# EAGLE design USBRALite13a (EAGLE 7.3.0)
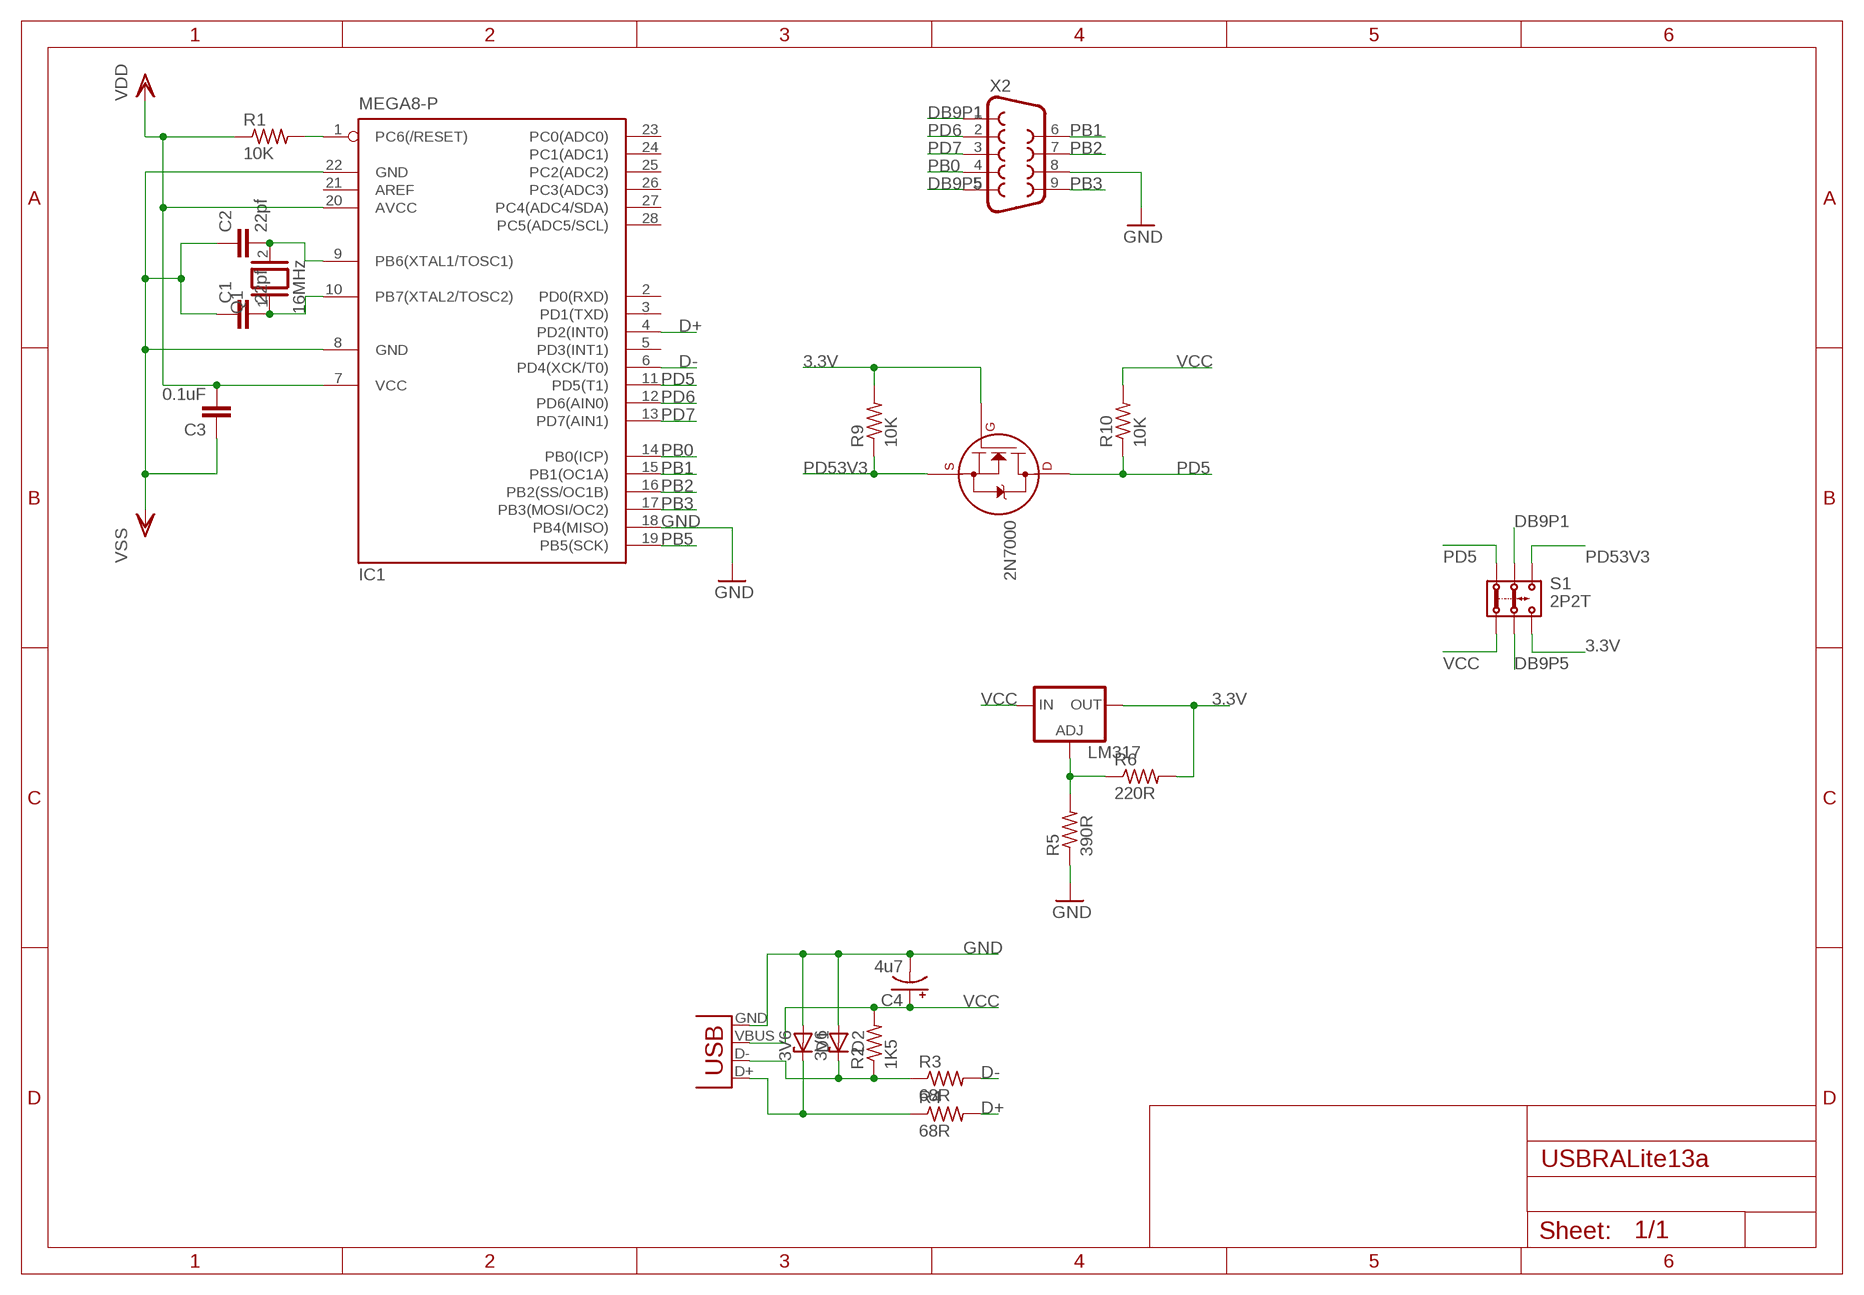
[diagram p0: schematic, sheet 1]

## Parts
2N7000  2N7000_TO92  [TO-92]
C1  22pf  C-EU050-024X044  [C050-024X044]
C2  22pf  C-EU050-024X044  [C050-024X044]
C3  0.1uF  C-EU050-024X044  [C050-024X044]
C4  4u7  CPOL-USE2.5-6  [E2,5-6]
D1  3V6  ZENER-DIODEZD-5  [ZDIO-5]
D2  3V6  ZENER-DIODEZD-5  [ZDIO-5]
IC1  MEGA8-P  [DIL28-3]
LM317  LM317TS  [317TS]
Q1  16MHz  XTAL/S  [QS]
R1  10K  R-US_0207/10  [0207/10]
R2  1K5  R-US_0207/10  [0207/10]
R3  68R  R-US_0207/10  [0207/10]
R4  68R  R-US_0207/10  [0207/10]
R5  390R  R-US_0207/10  [0207/10]
R6  220R  R-US_0207/10  [0207/10]
R9  10K  R-US_0207/10  [0207/10]
R10  10K  R-US_0207/10  [0207/10]
S1  2P2T  [2P2T]
X1  USBPTH  [USB-B-PTH]
X2  DB9MALE  [DB9_MALE]

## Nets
3.3V: 2N7000.2(G) LM317.2(OUT) R6.2 R9.2 S1.3.2
D+: IC1.4(PD2(INT0)) R4.2
D-: IC1.6(PD4(XCK/T0)) R3.2
DB9P1: S1.2.1 X2.1
DB9P5: S1.2.2 X2.5
GND: C1.1 C2.1 C3.1 C4.- D1.A D2.A IC1.8(GND) IC1.18(PB4(MISO)) IC1.22(GND) R5.1 X1.GND X2.8 ; supply symbol labelled VSS
N$1: IC1.1(PC6(/RESET)) R1.2
N$2: C2.2 IC1.9(PB6(XTAL1/TOSC1)) Q1.2
N$3: C1.2 IC1.10(PB7(XTAL2/TOSC2)) Q1.1
N$5: LM317.1(ADJ) R5.2 R6.1
N$8: D1.C R4.1 X1.D+
N$9: D2.C R2.1 R3.1 X1.D-
PB0: IC1.14(PB0(ICP)) X2.4
PB1: IC1.15(PB1(OC1A)) X2.6
PB2: IC1.16(PB2(SS/OC1B)) X2.7
PB3: IC1.17(PB3(MOSI/OC2)) X2.9
PB5: IC1.19(PB5(SCK))
PD5: 2N7000.3(D) IC1.11(PD5(T1)) R10.1 S1.1.1
PD6: IC1.12(PD6(AIN0)) X2.2
PD7: IC1.13(PD7(AIN1)) X2.3
PD53V3: 2N7000.1(S) R9.1 S1.3.1
VCC: C3.2 C4.+ IC1.7(VCC) IC1.20(AVCC) LM317.3(IN) R1.1 R2.2 R10.2 S1.1.2 X1.VBUS ; supply symbol labelled VDD
Unconnected: IC1.2(PD0(RXD)) IC1.3(PD1(TXD)) IC1.5(PD3(INT1)) IC1.21(AREF) IC1.23(PC0(ADC0)) IC1.24(PC1(ADC1)) IC1.25(PC2(ADC2)) IC1.26(PC3(ADC3)) IC1.27(PC4(ADC4/SDA)) IC1.28(PC5(ADC5/SCL))

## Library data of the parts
2N7000 = transistors:2N700*: 2N7000, 2N7002, NDS7002A N-channel enhancement mode MOSFET
C1-C3 = rcl:C-EU: CAPACITOR, European symbol
C4 = adafruit:CPOL-US: POLARIZED CAPACITOR, American symbol
D1 D2 = diode:ZENER-DIODE: Z-Diode
IC1 = atmel:MEGA8-P: MICROCONTROLLER 8 Kbytes FLASH, 1 kbytes SRAM, 512 bytes EEPROM, USART, 4-channel 10 bit ADC, 2-channel 8 bit ADC Pin compatible with Atmega48, ATMega88, ATMega168 Source: avr.lbr; OC_FARNELL: unknown; OC_NEWARK: unknown
LM317 = v-reg:LM317TS: VOLTAGE REGULATOR
Q1 = special:XTAL/S: CRYSTAL
R1-R6 R9 R10 = adafruit:R-US_: RESISTOR, American symbol
S1 = Itead_BP_110825:2P2T: BAS011
X1 = SparkFun:USB: USB Connectors USB-B-PTH is fully proven SKU : PRT-00139 USB-miniB is fully proven SKU : PRT-00587 USB-A-PCB is untested. USB-A-H is throughly reviewed, but untested. Spark Fun Electronics SKU : PRT-00437 USB-B-SMT is throughly reviewed, but untested. Needs silkscreen touching up. USB-A-S has not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
X2 = SparkFun:DB9: DB9 Connector Standard DB9 (D-Sub 9) serial connector. Can be used for CAN bus as well as RS485 and RS232. Footprint production proven. Spark Fun Electronics SKU : PRT-00429

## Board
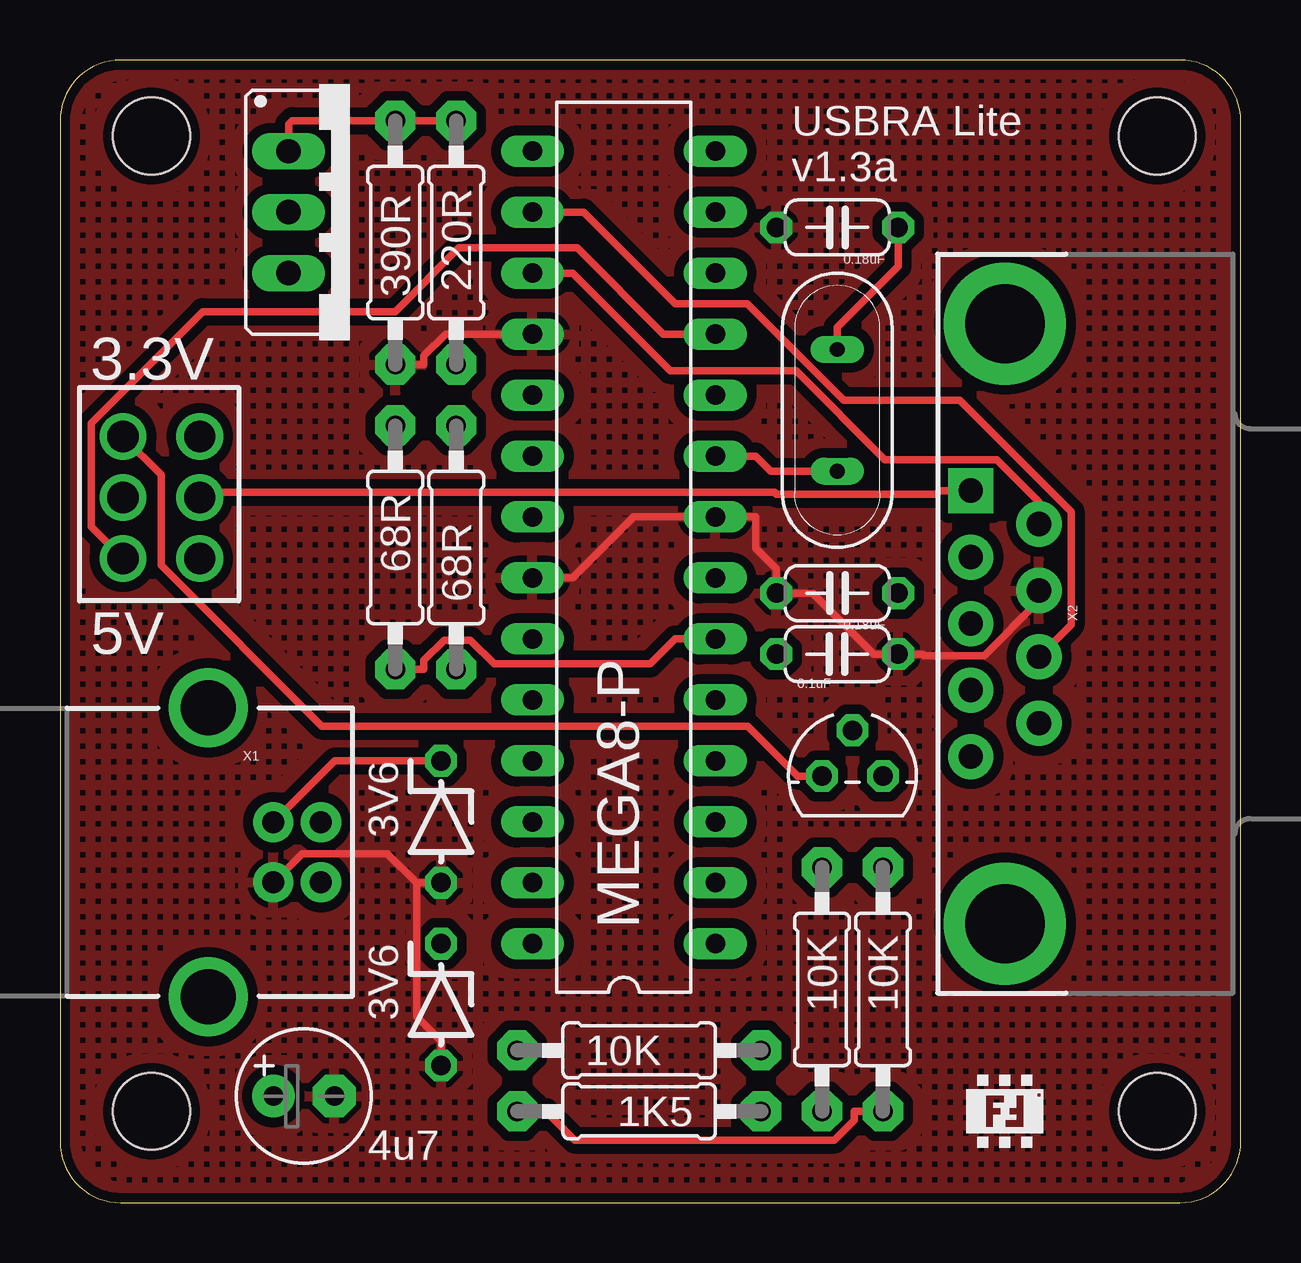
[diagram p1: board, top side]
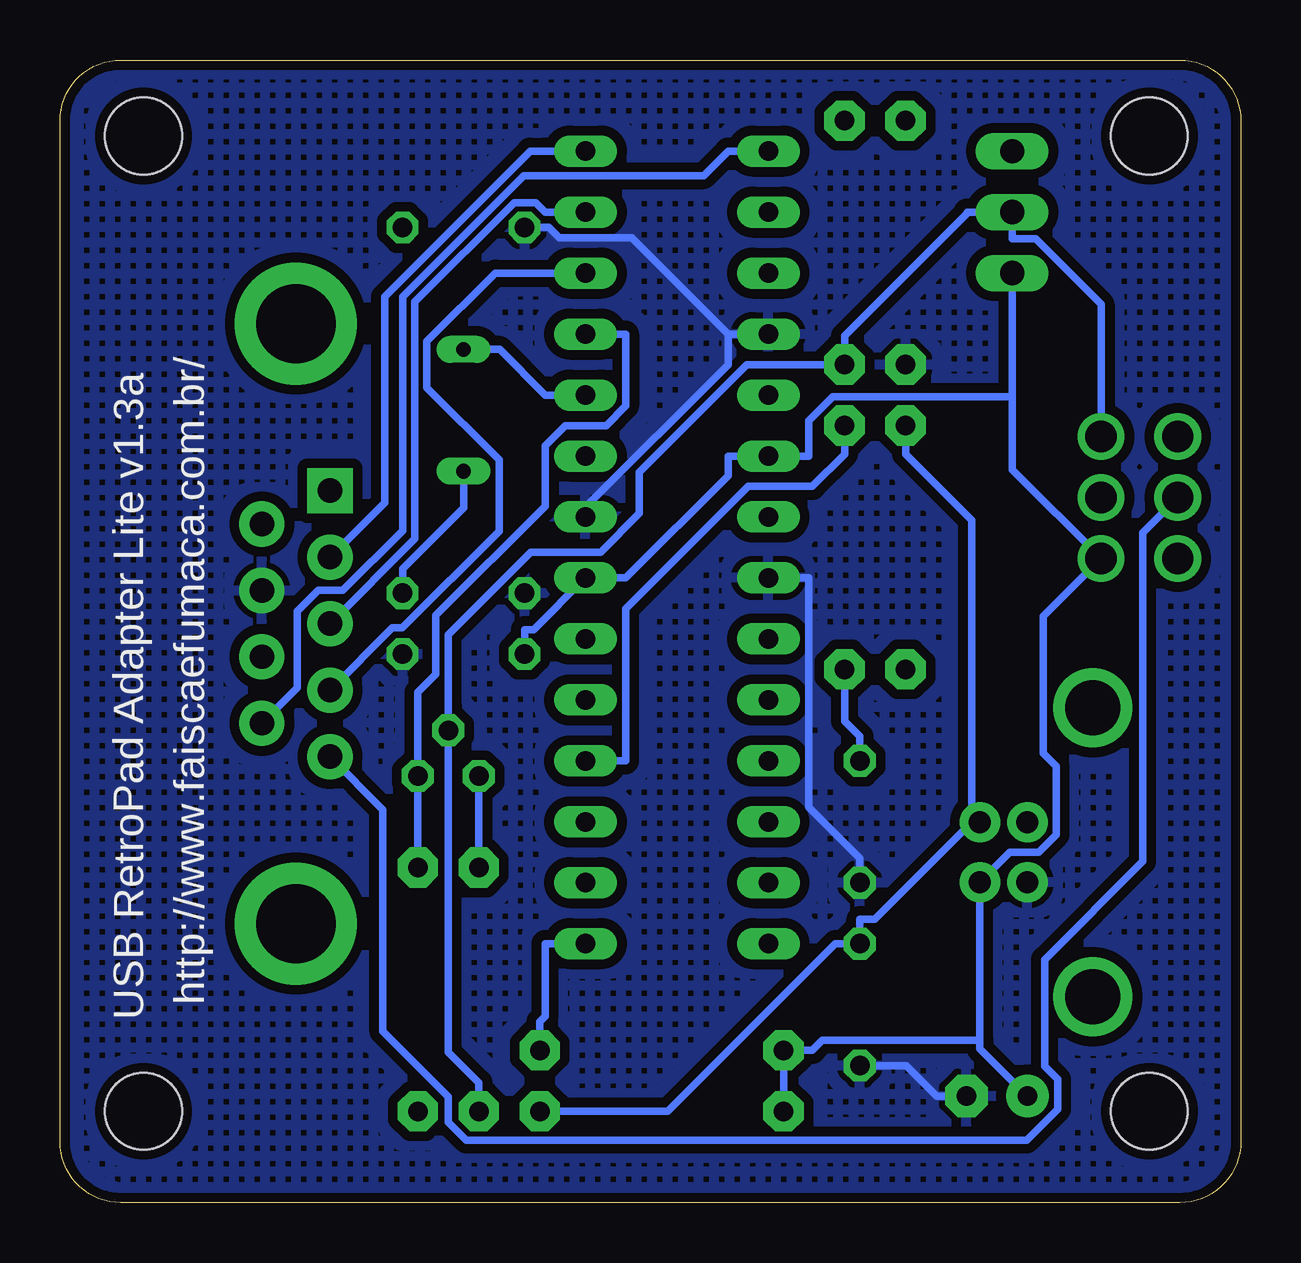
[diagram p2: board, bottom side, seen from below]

Size 49.2 x 47.62 mm. Coordinates in mm from the lower left corner, seen from the top.
Outline: 49.2,45.08 arc90 46.66,47.62 2.54,47.62 arc90 0,45.08 0,2.54 arc90 2.54,0 46.66,0 arc90 49.2,2.54 49.2,45.08
Copper layers (1*16): Top 0.035mm / dielectric 1.5mm / Bottom 0.035mm
Design rules "ITead_rule": minimum track width 6mil, minimum drill 12mil, track to track 6mil, track to pad 6mil, pad to pad 6mil, via to via 6mil, smd to smd 0mil, copper to edge 10mil, drill to drill 10mil, minimum pad ring 10mil, minimum via ring 6mil, stop-mask expansion 2mil, vias tented up to drill 100mil, thermal gap 10mil
Holes 3.2 mm at 3.81,44.45 3.81,3.81 45.72,44.45 45.72,3.81

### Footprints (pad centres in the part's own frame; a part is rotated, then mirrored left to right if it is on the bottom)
TO-92 = drill 0.813 octagon: 1 -1.27,0; 2 0,1.905; 3 1.27,0
C050-024X044 = drill 0.813 octagon: 1 -2.54,0; 2 2.54,0
E2,5-6 = drill 0.813 pad 1.778 round: + -1.27,0 | drill 0.813 pad 1.778 octagon: - 1.27,0
ZDIO-5 = drill 0.813 octagon: A 2.54,0; C -2.54,0
DIL28-3 = drill 0.813 long: 1 -16.51,-3.81; 2 -13.97,-3.81; 3 -11.43,-3.81; 4 -8.89,-3.81; 5 -6.35,-3.81; 6 -3.81,-3.81; 7 -1.27,-3.81; 8 1.27,-3.81; 9 3.81,-3.81; 10 6.35,-3.81; 11 8.89,-3.81; 12 11.43,-3.81; 13 13.97,-3.81; 14 16.51,-3.81; 15 16.51,3.81; 16 13.97,3.81; 17 11.43,3.81; 18 8.89,3.81; 19 6.35,3.81; 20 3.81,3.81; 21 1.27,3.81; 22 -1.27,3.81; 23 -3.81,3.81; 24 -6.35,3.81; 25 -8.89,3.81; 26 -11.43,3.81; 27 -13.97,3.81; 28 -16.51,3.81
317TS = drill 1.016 long: 1 -2.54,-2.54; 2 0,-2.54; 3 2.54,-2.54
QS = drill 0.61 long: 1 -2.54,0; 2 2.54,0
0207/10 = drill 0.813 pad 1.676 octagon: 1 -5.08,0; 2 5.08,0
2P2T = drill 1.3 pad 1.93 round: 1.1 -3.635,-0.085; 1.2 -3.635,-3.285; 2.1 -1.095,-0.085; 2.2 -1.095,-3.285; 3.1 1.445,-0.085; 3.2 1.445,-3.285
USB-B-PTH = drill 0.914 pad 1.676 round: D+ 0,1.25; D- 1.981,1.25; GND 0,-1.25; VBUS 1.981,-1.25 | drill 2.286 round: S1 -2.718,-6.02; S2 -2.718,6.02
DB9_MALE = drill 1.016 pad 1.88 round: 1 5.54,-1.42; 2 2.77,-1.42; 3 0,-1.42; 4 -2.77,-1.42; 6 4.15,1.42; 7 1.38,1.42; 8 -1.38,1.42; 9 -4.15,1.42 | drill 1.016 pad 1.88 square: 5 -5.54,-1.42 | drill 3.302 pad 5.08 round: G1 -12.5,0; G2 12.5,0

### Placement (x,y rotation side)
2N7000  33.02,17.78 0 top
C1  0.18uF  [C050-024X044]  32.38,40.64 0 top
C2  0.18uF  [C050-024X044]  32.38,25.4 0 top
C3  32.38,22.86 180 top
C4  10.16,4.45 0 top
D1  15.88,15.88 270 top
D2  15.88,8.26 270 top
IC1  23.5,27.3 90 top
LM317  12.06,41.27 270 top
Q1  32.38,33.02 270 top
R1  24.13,6.35 0 top
R2  24.13,3.81 180 top
R3  13.97,27.3 270 top
R4  16.51,27.3 90 top
R5  13.97,40.01 90 top
R6  16.51,40.01 270 top
R9  31.75,8.89 270 top
R10  34.29,8.89 270 top
S1  2.54,30.48 90 top
U$1  LOGOLOGO_WITHOUT_SMOKE_SMALL  [LOGO2_SMALL]  39.37,3.81 0 top
X1  8.89,14.61 0 top
X2  39.37,24.13 270 top

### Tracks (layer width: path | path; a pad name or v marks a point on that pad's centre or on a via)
3.3V
  Bottom 0.305: S1.3.2 5.83,37.44 8.55,40.16 9.53,40.16 LM317.2 11.4,41.27 11.4,41.22 16.51,36.12 R6.2 20.58,34.92 25.06,30.45 25.06,28.72 26.67,27.11 29.57,27.11 33.02,23.67 33.02,20.7 2N7000.2 33.02,6.27 31.75,5 R9.2
D+
  Bottom 0.305: IC1.4 25.63,18.41 25.63,24.74 20.52,29.84 17.86,29.84 16.51,31.19 R4.2
D-
  Top 0.305: IC1.6 25.63,23.5 24.59,22.45 18.09,22.45 17.1,23.44 16.01,23.44 15.16,22.6 15.16,22.23 R3.2
DB9P1
  Bottom 0.305: X2.1 35.74,16.38 35.74,7.14 33.02,4.42 33.02,3.36 32.27,2.6 8.92,2.6 7.63,3.9 7.63,5.14 8.18,5.69 8.18,10.13 4.09,14.22 4.09,27.92 S1.2.1
DB9P5
  Top 0.305: S1.2.2 6.04,29.59 29.78,29.59 29.85,29.53 36.51,29.53 36.65,29.67 X2.5
GND
  Top 0.305: X2.8 40.79,25.08 38.51,22.8 36,22.8 35.94,22.86 C3.1 33.91,22.86 31.37,25.4 C2.1 29.84,26.42 28.98,27.28 28.98,28.57 27.71,28.57 IC1.8 23.9,28.57 21.36,26.04 IC1.22 | R5.1 15.16,34.92 15.16,35.3 16.06,36.2 IC1.18 | 14.86,13.34 14.86,7.75 15.88,6.73 D2.A | 14.86,13.34 D1.A | X1.GND 10.09,14.55 13.64,14.55 14.86,13.34
  Bottom 0.305: C1.1 28.83,40.64 28.41,40.22 25.39,40.22 21.36,36.2 | IC1.8 27.3,28.98 21.36,34.92 21.36,36.2 | 21.36,36.2 IC1.18 | IC1.22 18.01,26.04 18.01,16.48 15.88,14.35 D1.A | C4.- 12.68,4.45 13.95,5.71 D2.A
  pour Bottom (isolate 0.406, hatched): 0,48.26 49.53,48.26 49.53,0 0,0
  pour Top (isolate 0.406, hatched): 0,48.26 49.53,48.26 49.53,0 0,0
N$1
  Bottom 0.305: IC1.1 28.98,10.79 28.98,7.77 29.21,7.54 R1.2
N$2
  Top 0.305: IC1.9 28.98,31.11 29.62,30.48 Q1.2
  Bottom 0.305: C2.2 34.92,26.42 32.38,28.96 Q1.2
N$3
  Top 0.305: Q1.1 32.38,36.47 34.92,39.01 C1.2
  Bottom 0.305: IC1.10 28.98,33.66 30.89,35.56 Q1.1
N$5
  Top 0.305: LM317.1 9.53,44.93 9.68,45.09 R5.2 R6.1
N$8
  Top 0.305: X1.D+ 11.45,18.41 D1.C
  Bottom 0.305: D1.C 15.88,19.43 16.51,20.07 R4.1
N$9
  Bottom 0.305: 11.21,15.86 11.21,28.43 13.97,31.19 R3.1 | 11.21,15.86 15.26,11.81 15.88,11.81 D2.C 16.89,10.79 23.88,3.81 28.02,3.81 R2.1 | 11.21,15.86 X1.D-
PB0
  Bottom 0.305: X2.4 35.67,29.17 35.67,37.75 29.61,43.81 28.98,43.81 IC1.14
PB1
  Bottom 0.305: IC1.15 21.36,43.81 22.38,42.8 29.87,42.8 34.92,37.74 34.92,28 37.41,25.52 38.44,25.52 39.32,24.64 39.32,21.45 X2.6
PB2
  Top 0.305: X2.7 42.13,24.09 42.13,28.8 37.49,33.43 32.66,33.43 28.63,37.47 25.63,37.47 21.82,41.27 IC1.16
PB3
  Top 0.305: IC1.17 21.36,38.73 25.43,34.67 30.67,34.67 34.38,30.97 39.04,30.97 40.79,29.21 X2.9
PD5
  Top 0.305: S1.1.1 1.29,28.18 1.29,32.48 5.94,37.13 13.97,37.13 16.62,39.78 21.56,39.78 25.15,36.2 IC1.11
  Bottom 0.305: IC1.11 25.63,36.2 25.63,33.2 26.45,32.38 28.14,32.38 28.98,31.54 28.98,29.03 33.54,24.47 33.54,22.02 34.29,21.27 2N7000.3 R10.1
PD6
  Bottom 0.305: X2.2 35.36,23.95 34.94,23.95 30.9,27.99 30.9,30.95 33.91,33.96 33.91,35.89 31.06,38.73 IC1.12
PD7
  Bottom 0.305: IC1.13 28.98,41.27 29.38,41.67 30.27,41.67 34.42,37.53 34.42,27.66 X2.3
PD53V3
  Top 0.305: 2N7000.1 30.73,17.78 28.65,19.86 10.91,19.86 4.22,26.55 4.22,30.32 S1.3.1
  Bottom 0.305: 2N7000.1 R9.1
VCC
  Top 0.305: R10.2 33.1,3.81 33.1,3.44 32.27,2.61 21.45,2.61 20.24,3.81 R2.2
  Bottom 0.305: 9.53,33.59 9.53,30.55 S1.1.2 8.23,24.44 8.23,18.73 7.69,18.2 7.69,15.34 8.42,14.61 9.62,14.61 X1.VBUS 10.87,6.77 | 9.53,33.59 LM317.3 | 9.53,33.59 17,33.59 18.01,32.58 18.01,31.11 IC1.20 21.36,31.11 21.36,30.3 25.63,26.04 IC1.7 29.46,23.88 29.84,23.88 C3.2 | 10.87,6.77 10.87,6.43 C4.+ | 10.87,6.77 17.44,6.77 17.86,6.35 R1.1 R2.2

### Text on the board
tPlace: USBRA Lite | v1.3a | 3.3V | 5V
bPlace: http://www.faiscaefumaca.com.br/ | USB RetroPad Adapter Lite v1.3a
